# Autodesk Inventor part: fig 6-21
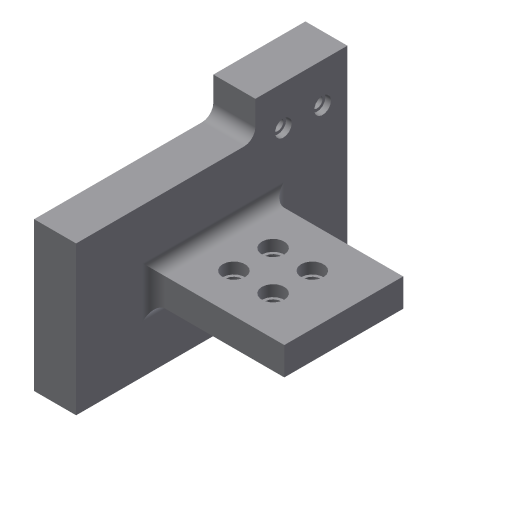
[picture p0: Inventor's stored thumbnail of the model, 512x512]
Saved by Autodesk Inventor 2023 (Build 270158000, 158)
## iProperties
Created: 2004-05
Part Number: fig 6-21
Document SubType Name: Modeling
Designer: CADCIM Technologies
Manufacturer: Standard
Standards Organization: Custom
Density: 1 g/cm^3
Material: Generic
Appearance: Default
Author: CADCIM Technologies
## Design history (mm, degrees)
node "Sketch1"
sketch "Sketch2"
  geometry: L1 (0, 0)-(0, 26.557); L2 (0, 26.557)-(31.986, 26.557); L3 (31.986, 26.557)-(31.986, 32.916); L4 (31.986, 32.916)-(48.42, 32.916); L5 (48.42, 32.916)-(48.42, 0); L6 (48.42, 0)-(0, 0)
  constraints: 12 end point, 4 parallel, 1 perpendicular, 1 vertical
extrude "Extrusion1" new body sketch "Sketch2" distance "d0" = 7.5; taper "d1" = 0 deg
workplane "Work Plane1"
sketch "Sketch3"
  geometry: L1 (7.5, 35.088)-(30.78, 35.088); L2 (30.78, 35.088)-(30.78, 13.871); L3 (30.78, 13.871)-(7.5, 13.871); L4 (7.5, 31.986)-(7.5, 48.42) reference; L5 (7.5, 0)-(7.5, 31.986) reference
  constraints: 6 end point, 2 point on line, 1 horizontal, 1 parallel, 1 perpendicular
extrude "Extrusion2" join sketch "Sketch3" distance "d3" = 5; taper "d4" = 0 deg
fillet "Fillet2" dims "d7" = 2
fillet "Fillet3" dims "d8" = 2
hole "Hole1" diameter "d11" = 3; stored, may be unused: countersink angle "d15" = 90 deg, drill point angle "d17" = 118 deg; dims "d9" = 7, "d10" = 16, "d12" = 6, "d13" = 4, "d14" = 2, "d16" = 8
pattern_linear "Rectangular Pattern1" dims "d20" = 7, "d23" = 7
hole "Hole2" diameter "d26" = 2; stored, may be unused: countersink angle "d30" = 90 deg, drill point angle "d32" = 118 deg; dims "d24" = 5, "d25" = 7, "d27" = 6, "d28" = 3, "d29" = 1, "d31" = 8
pattern_linear "Rectangular Pattern2" dims "d35" = 7
body "Solid1"
other parameters: "d2" = -11
